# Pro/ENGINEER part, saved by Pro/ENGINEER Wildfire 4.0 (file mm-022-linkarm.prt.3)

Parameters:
  METRIC = "NO"

Other parameters: PITCH, DRILL_DIAMETER, THREAD_DIAMETER, THREADS_PER_INCH, THREAD_DEPTH, THREAD_LENGTH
